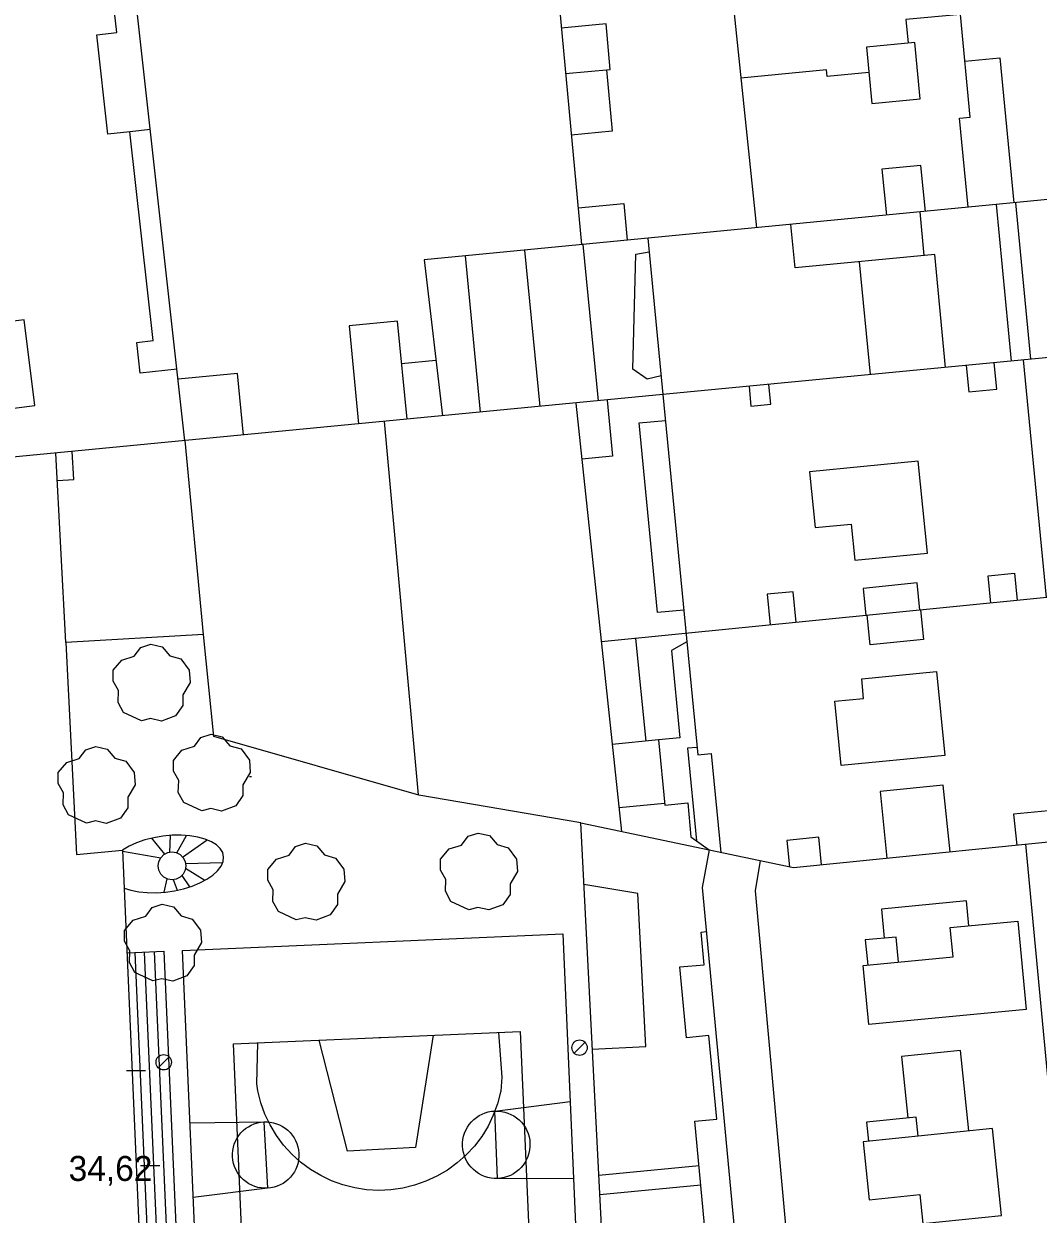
# Model space of a CAD drawing. Extents: x 431390 to 432653, y 4586754 to 4589600.
# Drawn here: x 431796.9 to 431849.6, y 4586938.4 to 4587000.3 of the extents above; entities that cross this region are included whole.
import ezdxf

# ---------------------------------------------------------------- set-up
doc = ezdxf.new("R2010")
doc.units = 0
for name, color, linetype in [('CON_01FI_LN', 7, 'Continuous'), ('CON_03_LN', 7, 'Continuous'), ('CON_04_LN', 7, 'Continuous'), ('CON_18LS_LN', 7, 'Continuous'), ('CON_23_LN', 7, 'Continuous'), ('CON_24LS_LN', 7, 'Continuous'), ('CON_29_LN', 7, 'Continuous'), ('ENE_06_PT', 7, 'Continuous'), ('ORO_03_PT', 7, 'Continuous'), ('ORO_04_PT', 7, 'Continuous'), ('ORO_04_TX', 7, 'Continuous'), ('VEG_03_PT', 7, 'Continuous')]:
    doc.layers.add(name, color=color, linetype=linetype)

msp = doc.modelspace()

# ---------------------------------------------------------------- linework, layer by layer
at = {"layer": 'CON_01FI_LN'}
msp.add_lwpolyline([(431827.13, 4586932.71), (431825.8, 4586958.75), (431817.38, 4586960.2), (431806.73, 4586963.25), (431806.19, 4586968.54), (431799.05, 4586968.14), (431799.59, 4586957.11), (431801.98, 4586957.34), (431806.03, 4586864.43)], dxfattribs=at)
at = {"layer": 'CON_03_LN'}
for points in [[(431816.997, 4587024.756), (431817.92, 4587018.02), (431821.03, 4587018.37), (431823.45, 4587014.45), (431824.464, 4587003.566), (431825.837, 4586988.819)], [(431805.234, 4586978.625), (431800.299, 4587023.109)], [(431850.776, 4586991.226), (431817.66, 4586988.03), (431818.619, 4586979.915)], [(431851.584, 4586983.093), (431830.073, 4586981.019), (431784.22, 4586976.6)], [(431825.548, 4586980.583), (431827.924, 4586958.305)], [(431852.81, 4586970.754), (431826.872, 4586968.172)], [(431825.8, 4586958.75), (431832.476, 4586957.35), (431836.86, 4586956.43), (431854.062, 4586958.16)]]:
    msp.add_lwpolyline(points, dxfattribs=at)
at = {"layer": 'CON_04_LN'}
for points in [[(431833.389, 4587004.496), (431834.928, 4586989.697)], [(431804.822, 4586982.339), (431802.903, 4586982.126), (431802.725, 4586983.735), (431803.577, 4586983.829), (431802.372, 4586994.689), (431801.223, 4586994.562), (431800.65, 4586999.726), (431801.69, 4586999.841), (431801.386, 4587002.577), (431802.562, 4587002.707)], [(431845.931, 4586990.758), (431845.485, 4586995.383), (431846.043, 4586995.437), (431845.527, 4587000.788), (431842.693, 4587000.515), (431842.812, 4586999.284)], [(431825.009, 4586997.708), (431827.334, 4586997.925), (431827.113, 4587000.294), (431824.789, 4587000.078)], [(431843.439, 4586996.39), (431843.156, 4586999.317), (431840.642, 4586999.074), (431840.924, 4586996.147), (431843.439, 4586996.39)], [(431845.762, 4586998.35), (431847.575, 4586998.525), (431848.302, 4586990.987)], [(431827.133, 4586997.906), (431827.433, 4586994.709), (431825.307, 4586994.51)], [(431840.768, 4586997.77), (431838.608, 4586997.562), (431838.575, 4586997.9), (431834.12, 4586997.471)], [(431803.439, 4586994.807), (431802.372, 4586994.689)], [(431843.712, 4586990.544), (431843.481, 4586992.939), (431841.45, 4586992.743), (431841.681, 4586990.348)], [(431825.659, 4586990.733), (431828.037, 4586990.954), (431828.214, 4586989.049)], [(431843.651, 4586988.252), (431843.433, 4586990.517)], [(431848.187, 4586982.765), (431847.402, 4586990.9)], [(431849.188, 4586982.862), (431848.404, 4586990.997)], [(431844.759, 4586982.435), (431844.193, 4586988.304), (431836.94, 4586987.605), (431836.722, 4586989.87)], [(431825.915, 4586988.827), (431826.7, 4586980.694)], [(431829.288, 4586989.152), (431830.073, 4586981.019), (431831.879, 4586962.301), (431832.582, 4586962.369), (431833.079, 4586957.223)], [(431819.788, 4586988.235), (431820.574, 4586980.104)], [(431829.979, 4586981.988), (431829.26, 4586981.82), (431828.51, 4586982.35), (431828.66, 4586988.32), (431829.356, 4586988.448)], [(431796.876, 4586984.9), (431791, 4586984.16), (431791.56, 4586979.712), (431797.436, 4586980.452), (431796.876, 4586984.9)], [(431816.772, 4586979.737), (431816.281, 4586984.83), (431813.766, 4586984.588), (431814.257, 4586979.495)], [(431816.492, 4586982.642), (431818.276, 4586982.814)], [(431845.828, 4586982.538), (431845.961, 4586981.158), (431847.421, 4586981.299), (431847.288, 4586982.679)], [(431848.791, 4586982.824), (431849.981, 4586970.472)], [(431808.268, 4586978.918), (431807.96, 4586982.117), (431804.88, 4586981.82)], [(431834.546, 4586981.45), (431834.646, 4586980.417), (431835.679, 4586980.517), (431835.579, 4586981.55)], [(431827.165, 4586980.739), (431827.447, 4586977.818), (431825.859, 4586977.665)], [(431831.153, 4586969.821), (431829.787, 4586969.689), (431828.835, 4586979.55), (431830.202, 4586979.682)], [(431798.605, 4586976.554), (431799.453, 4586976.599), (431799.376, 4586978.061)], [(431806.19, 4586968.54), (431805.249, 4586978.627)], [(431799.05, 4586968.14), (431798.53, 4586977.979)], [(431843.815, 4586972.785), (431843.338, 4586977.568), (431837.693, 4586977.006), (431837.982, 4586974.107), (431839.852, 4586974.293), (431840.04, 4586972.409), (431843.815, 4586972.785)], [(431847.105, 4586970.186), (431846.964, 4586971.607), (431848.336, 4586971.744), (431848.477, 4586970.323)], [(431836.998, 4586969.18), (431836.84, 4586970.771), (431835.49, 4586970.637), (431835.648, 4586969.046)], [(431843.429, 4586969.82), (431843.289, 4586971.226), (431840.483, 4586970.947), (431840.623, 4586969.541)], [(431843.459, 4586969.823), (431843.612, 4586968.281), (431840.841, 4586968.005), (431840.688, 4586969.547)], [(431828.653, 4586968.349), (431829.185, 4586963.007)], [(431831.313, 4586968.167), (431830.52, 4586967.71), (431830.957, 4586963.178), (431829.84, 4586963.07), (431830.168, 4586959.675), (431831.359, 4586959.79), (431831.529, 4586958.031), (431832.476, 4586957.35)], [(431844.286, 4586966.624), (431844.72, 4586962.266), (431839.332, 4586961.73), (431838.999, 4586965.077), (431840.499, 4586965.226), (431840.398, 4586966.237), (431844.286, 4586966.624)], [(431829.84, 4586963.07), (431827.44, 4586962.838)], [(431831.842, 4586962.681), (431831.348, 4586962.633), (431831.81, 4586957.829)], [(431844.989, 4586957.248), (431844.64, 4586960.72), (431841.358, 4586960.39), (431841.707, 4586956.917)], [(431830.16, 4586959.757), (431827.793, 4586959.53)], [(431850.263, 4586957.778), (431850.101, 4586959.387), (431848.294, 4586959.205), (431848.456, 4586957.596)], [(431838.319, 4586956.577), (431838.175, 4586958.008), (431836.513, 4586957.841), (431836.651, 4586956.474)], [(431848.912, 4586957.642), (431851.315, 4586932.152)], [(431832.476, 4586957.35), (431832.11, 4586955.39), (431834.252, 4586932.546)], [(431835.115, 4586956.796), (431834.86, 4586955.22), (431836.918, 4586932.484)], [(431826.4, 4586946.993), (431829.177, 4586947.135), (431828.771, 4586955.079), (431825.963, 4586955.557)], [(431845.971, 4586953.402), (431845.849, 4586954.694), (431841.431, 4586954.277), (431841.574, 4586952.763)], [(431848.944, 4586949.048), (431840.763, 4586948.277), (431840.474, 4586951.342), (431845.149, 4586951.783), (431845.005, 4586953.311), (431848.511, 4586953.642), (431848.944, 4586949.048)], [(431834.195, 4586933.154), (431833.853, 4586933.122), (431833.519, 4586936.676), (431832.357, 4586936.567), (431831.729, 4586943.247), (431832.87, 4586943.354), (431832.462, 4586947.694), (431831.302, 4586947.585), (431830.956, 4586951.263), (431832.219, 4586951.382), (431832.06, 4586953.075), (431832.325, 4586953.1)], [(431842.319, 4586951.516), (431842.196, 4586952.822), (431840.588, 4586952.67), (431840.711, 4586951.364)], [(431845.964, 4586942.744), (431845.534, 4586946.922), (431842.469, 4586946.607), (431842.797, 4586943.418)], [(431843.334, 4586942.474), (431843.232, 4586943.463), (431840.65, 4586943.198), (431840.752, 4586942.209)], [(431847.196, 4586942.871), (431840.47, 4586942.18), (431840.78, 4586939.161), (431843.421, 4586939.432), (431843.575, 4586937.932), (431847.66, 4586938.351), (431847.196, 4586942.871)], [(431831.948, 4586940.918), (431826.736, 4586940.428)], [(431832.042, 4586939.917), (431826.787, 4586939.423)]]:
    msp.add_lwpolyline(points, dxfattribs=at)
at = {"layer": 'CON_18LS_LN'}
for points in [[(431802.213, 4586952.001), (431802.637, 4586952.019), (431804.137, 4586952.084), (431805.827, 4586913.305), (431804.327, 4586913.24), (431803.903, 4586913.221)], [(431803.637, 4586952.062), (431805.327, 4586913.283)], [(431802.637, 4586952.019), (431804.327, 4586913.24)], [(431804.827, 4586913.262), (431803.137, 4586952.041)]]:
    msp.add_lwpolyline(points, dxfattribs=at)
at = {"layer": 'CON_23_LN'}
for points in [[(431802.066, 4586955.365), (431802.426, 4586955.25), (431802.831, 4586955.17), (431803.273, 4586955.127), (431803.739, 4586955.121), (431804.217, 4586955.154), (431804.696, 4586955.224), (431805.163, 4586955.33), (431805.606, 4586955.468), (431806.015, 4586955.636), (431806.378, 4586955.829), (431806.686, 4586956.041), (431806.932, 4586956.269), (431807.11, 4586956.505), (431807.214, 4586956.745), (431807.242, 4586956.981), (431807.194, 4586957.208), (431807.07, 4586957.42), (431806.874, 4586957.611), (431806.611, 4586957.777), (431806.287, 4586957.914), (431805.911, 4586958.018), (431805.492, 4586958.086), (431805.042, 4586958.117), (431804.57, 4586958.109), (431804.09, 4586958.064), (431803.614, 4586957.982), (431803.153, 4586957.865), (431802.72, 4586957.716), (431802.326, 4586957.54), (431801.98, 4586957.34)], [(431804.181, 4586957.128), (431803.51, 4586957.956)], [(431804.44, 4586957.223), (431804.488, 4586958.101)], [(431804.811, 4586957.194), (431805.306, 4586958.099)], [(431805.113, 4586956.978), (431806.396, 4586957.868)], [(431801.983, 4586957.282), (431803.973, 4586956.938)], [(431805.284, 4586956.52), (431805.249, 4586956.297), (431805.146, 4586956.095), (431804.986, 4586955.935), (431804.785, 4586955.833), (431804.561, 4586955.797), (431804.338, 4586955.833), (431804.136, 4586955.935), (431803.977, 4586956.095), (431803.874, 4586956.297), (431803.838, 4586956.52), (431803.874, 4586956.743), (431803.977, 4586956.945), (431804.136, 4586957.105), (431804.338, 4586957.207), (431804.561, 4586957.243), (431804.785, 4586957.207), (431804.986, 4586957.105), (431805.146, 4586956.945), (431805.249, 4586956.743), (431805.284, 4586956.52)], [(431805.264, 4586956.395), (431806.275, 4586955.774)], [(431805.265, 4586956.641), (431807.193, 4586956.696)], [(431804.156, 4586955.15), (431804.311, 4586955.847)], [(431804.618, 4586955.806), (431804.837, 4586955.256)], [(431805.064, 4586956.013), (431805.462, 4586955.423)]]:
    msp.add_lwpolyline(points, dxfattribs=at)
at = {"layer": 'CON_24LS_LN'}
for points in [[(431805.108, 4586952.126), (431824.867, 4586952.987), (431826.566, 4586914.02), (431806.807, 4586913.159), (431805.108, 4586952.126)], [(431807.75, 4586947.261), (431822.646, 4586947.91), (431823.859, 4586920.092), (431808.963, 4586919.443), (431807.75, 4586947.261)], [(431821.527, 4586947.861), (431821.705, 4586945.539), (431821.646, 4586944.815), (431821.636, 4586944.751), (431821.475, 4586944.143), (431821.256, 4586943.554), (431820.981, 4586942.989), (431820.652, 4586942.453), (431820.273, 4586941.953), (431819.846, 4586941.491), (431819.377, 4586941.073), (431818.869, 4586940.704), (431818.327, 4586940.385), (431817.757, 4586940.121), (431817.163, 4586939.913), (431816.553, 4586939.764), (431815.931, 4586939.676), (431815.303, 4586939.649), (431814.675, 4586939.683), (431814.054, 4586939.778), (431813.445, 4586939.933), (431812.854, 4586940.147), (431812.287, 4586940.417), (431811.749, 4586940.741), (431811.244, 4586941.116), (431810.779, 4586941.539), (431810.358, 4586942.005), (431809.983, 4586942.51), (431809.66, 4586943.049), (431809.391, 4586943.617), (431809.178, 4586944.208), (431809.024, 4586944.817), (431808.969, 4586945.183), (431809.016, 4586947.316)], [(431818.137, 4586947.714), (431817.21, 4586941.88), (431813.68, 4586941.69), (431812.2, 4586947.455)], [(431825.422, 4586940.257), (431821.48, 4586940.27), (431821.339, 4586943.776), (431825.247, 4586944.264)], [(431821.48, 4586940.27), (431821.308, 4586940.272), (431821.137, 4586940.29), (431820.968, 4586940.325), (431820.804, 4586940.376), (431820.645, 4586940.444), (431820.494, 4586940.526), (431820.352, 4586940.623), (431820.22, 4586940.734), (431820.099, 4586940.856), (431819.991, 4586940.99), (431819.897, 4586941.134), (431819.817, 4586941.287), (431819.752, 4586941.447), (431819.704, 4586941.612), (431819.672, 4586941.781), (431819.657, 4586941.952), (431819.658, 4586942.125), (431819.676, 4586942.296), (431819.712, 4586942.464), (431819.763, 4586942.629), (431819.83, 4586942.787), (431819.913, 4586942.938), (431820.01, 4586943.081), (431820.12, 4586943.213), (431820.243, 4586943.333), (431820.377, 4586943.441), (431820.521, 4586943.536), (431820.674, 4586943.616), (431820.833, 4586943.68), (431820.998, 4586943.729), (431821.168, 4586943.761), (431821.339, 4586943.776), (431821.511, 4586943.774), (431821.682, 4586943.756), (431821.851, 4586943.721), (431822.015, 4586943.67), (431822.174, 4586943.602), (431822.325, 4586943.52), (431822.467, 4586943.423), (431822.599, 4586943.312), (431822.72, 4586943.19), (431822.828, 4586943.056), (431822.922, 4586942.912), (431823.002, 4586942.759), (431823.067, 4586942.599), (431823.115, 4586942.434), (431823.147, 4586942.265), (431823.162, 4586942.094), (431823.161, 4586941.921), (431823.143, 4586941.75), (431823.107, 4586941.582), (431823.056, 4586941.417), (431822.989, 4586941.259), (431822.906, 4586941.108), (431822.809, 4586940.965), (431822.699, 4586940.833), (431822.576, 4586940.713), (431822.442, 4586940.605), (431822.298, 4586940.51), (431822.145, 4586940.43), (431821.986, 4586940.366), (431821.821, 4586940.317), (431821.651, 4586940.285), (431821.48, 4586940.27)], [(431805.499, 4586943.169), (431809.33, 4586943.21), (431809.53, 4586939.76), (431805.668, 4586939.271)], [(431809.33, 4586943.21), (431809.5, 4586943.211), (431809.668, 4586943.196), (431809.835, 4586943.165), (431809.998, 4586943.117), (431810.155, 4586943.053), (431810.305, 4586942.975), (431810.447, 4586942.882), (431810.579, 4586942.775), (431810.7, 4586942.657), (431810.809, 4586942.527), (431810.904, 4586942.386), (431810.985, 4586942.238), (431811.052, 4586942.081), (431811.102, 4586941.92), (431811.137, 4586941.754), (431811.155, 4586941.585), (431811.156, 4586941.415), (431811.141, 4586941.247), (431811.11, 4586941.08), (431811.062, 4586940.917), (431810.998, 4586940.76), (431810.92, 4586940.61), (431810.827, 4586940.468), (431810.72, 4586940.336), (431810.602, 4586940.215), (431810.472, 4586940.106), (431810.331, 4586940.011), (431810.183, 4586939.93), (431810.026, 4586939.863), (431809.865, 4586939.813), (431809.699, 4586939.778), (431809.53, 4586939.76), (431809.36, 4586939.759), (431809.192, 4586939.774), (431809.025, 4586939.805), (431808.862, 4586939.853), (431808.705, 4586939.917), (431808.555, 4586939.995), (431808.413, 4586940.088), (431808.281, 4586940.195), (431808.16, 4586940.313), (431808.051, 4586940.443), (431807.956, 4586940.584), (431807.875, 4586940.732), (431807.808, 4586940.889), (431807.758, 4586941.05), (431807.723, 4586941.216), (431807.705, 4586941.385), (431807.704, 4586941.555), (431807.719, 4586941.723), (431807.75, 4586941.89), (431807.798, 4586942.053), (431807.862, 4586942.21), (431807.94, 4586942.36), (431808.033, 4586942.502), (431808.14, 4586942.634), (431808.258, 4586942.755), (431808.388, 4586942.864), (431808.529, 4586942.959), (431808.677, 4586943.04), (431808.834, 4586943.107), (431808.995, 4586943.157), (431809.161, 4586943.192), (431809.33, 4586943.21)]]:
    msp.add_lwpolyline(points, dxfattribs=at)
at = {"layer": 'CON_29_LN'}
for points in [[(431822.884, 4586988.534), (431823.669, 4586980.402)], [(431840.276, 4586987.926), (431840.841, 4586982.057)], [(431815.582, 4586979.622), (431817.352, 4586960.208)]]:
    msp.add_lwpolyline(points, dxfattribs=at)
at = {"layer": 'ENE_06_PT'}
for p, q in [((431826.022, 4586947.352), (431825.456, 4586946.786)), ((431804.412, 4586946.592), (431803.846, 4586946.026))]:
    msp.add_line(p, q, dxfattribs=at)
for centre in [(431825.739, 4586947.069), (431804.129, 4586946.309)]:
    msp.add_circle(centre, 0.4, dxfattribs=at)
at = {"layer": 'ORO_03_PT'}
for p, q in [((431808.59, 4586961.16), (431808.69, 4586961.16)), ((431815.316, 4586947.593), (431815.416, 4586947.593))]:
    msp.add_line(p, q, dxfattribs=at)
at = {"layer": 'ORO_04_PT'}
for p, q in [((431802.19, 4586945.89), (431803.19, 4586945.89)), ((431802.92, 4586940.95), (431803.92, 4586940.95))]:
    msp.add_line(p, q, dxfattribs=at)
at = {"layer": 'VEG_03_PT'}
for points in [[(431802.974, 4586964.061), (431802.047, 4586964.496), (431801.759, 4586965.017), (431801.782, 4586965.631), (431801.5, 4586966.123), (431801.508, 4586966.686), (431801.949, 4586967.221), (431802.602, 4586967.425), (431802.937, 4586967.876), (431803.463, 4586968.046), (431804.043, 4586967.913), (431804.443, 4586967.447), (431805.017, 4586967.277), (431805.451, 4586966.694), (431805.5, 4586966.052), (431805.117, 4586965.405), (431805.117, 4586964.855), (431804.745, 4586964.321), (431804.006, 4586964.046), (431803.441, 4586964.174), (431802.974, 4586964.061)], [(431806.104, 4586959.381), (431805.177, 4586959.816), (431804.889, 4586960.337), (431804.912, 4586960.951), (431804.63, 4586961.443), (431804.638, 4586962.006), (431805.079, 4586962.541), (431805.732, 4586962.745), (431806.067, 4586963.196), (431806.593, 4586963.366), (431807.173, 4586963.233), (431807.573, 4586962.767), (431808.147, 4586962.597), (431808.581, 4586962.014), (431808.63, 4586961.372), (431808.247, 4586960.725), (431808.247, 4586960.175), (431807.875, 4586959.641), (431807.136, 4586959.366), (431806.571, 4586959.494), (431806.104, 4586959.381)], [(431800.114, 4586958.741), (431799.187, 4586959.176), (431798.899, 4586959.697), (431798.922, 4586960.311), (431798.64, 4586960.803), (431798.648, 4586961.366), (431799.089, 4586961.901), (431799.742, 4586962.105), (431800.077, 4586962.556), (431800.603, 4586962.726), (431801.183, 4586962.593), (431801.583, 4586962.127), (431802.157, 4586961.957), (431802.591, 4586961.374), (431802.64, 4586960.732), (431802.257, 4586960.085), (431802.257, 4586959.535), (431801.885, 4586959.001), (431801.146, 4586958.726), (431800.581, 4586958.854), (431800.114, 4586958.741)], [(431811.014, 4586953.711), (431810.087, 4586954.146), (431809.799, 4586954.667), (431809.822, 4586955.281), (431809.54, 4586955.773), (431809.548, 4586956.336), (431809.989, 4586956.871), (431810.642, 4586957.075), (431810.977, 4586957.526), (431811.503, 4586957.696), (431812.083, 4586957.563), (431812.483, 4586957.097), (431813.057, 4586956.927), (431813.491, 4586956.344), (431813.54, 4586955.702), (431813.157, 4586955.055), (431813.157, 4586954.505), (431812.785, 4586953.971), (431812.046, 4586953.696), (431811.481, 4586953.824), (431811.014, 4586953.711)], [(431819.984, 4586954.241), (431819.057, 4586954.676), (431818.769, 4586955.197), (431818.792, 4586955.811), (431818.51, 4586956.303), (431818.518, 4586956.866), (431818.959, 4586957.401), (431819.612, 4586957.605), (431819.947, 4586958.056), (431820.473, 4586958.226), (431821.053, 4586958.093), (431821.453, 4586957.627), (431822.027, 4586957.457), (431822.461, 4586956.874), (431822.51, 4586956.232), (431822.127, 4586955.585), (431822.127, 4586955.035), (431821.755, 4586954.501), (431821.016, 4586954.226), (431820.451, 4586954.354), (431819.984, 4586954.241)], [(431803.564, 4586950.541), (431802.637, 4586950.976), (431802.349, 4586951.497), (431802.372, 4586952.111), (431802.09, 4586952.603), (431802.098, 4586953.166), (431802.539, 4586953.701), (431803.192, 4586953.905), (431803.527, 4586954.356), (431804.053, 4586954.526), (431804.633, 4586954.393), (431805.033, 4586953.927), (431805.607, 4586953.757), (431806.041, 4586953.174), (431806.09, 4586952.532), (431805.707, 4586951.885), (431805.707, 4586951.335), (431805.335, 4586950.801), (431804.596, 4586950.526), (431804.031, 4586950.654), (431803.564, 4586950.541)]]:
    msp.add_lwpolyline(points, dxfattribs=at)

# ---------------------------------------------------------------- texts
at = {"layer": 'ORO_04_TX'}
msp.add_text('34,62', height=1.3, dxfattribs=at).set_placement((431799.19, 4586940.14))

doc.saveas('drawing.dxf')
